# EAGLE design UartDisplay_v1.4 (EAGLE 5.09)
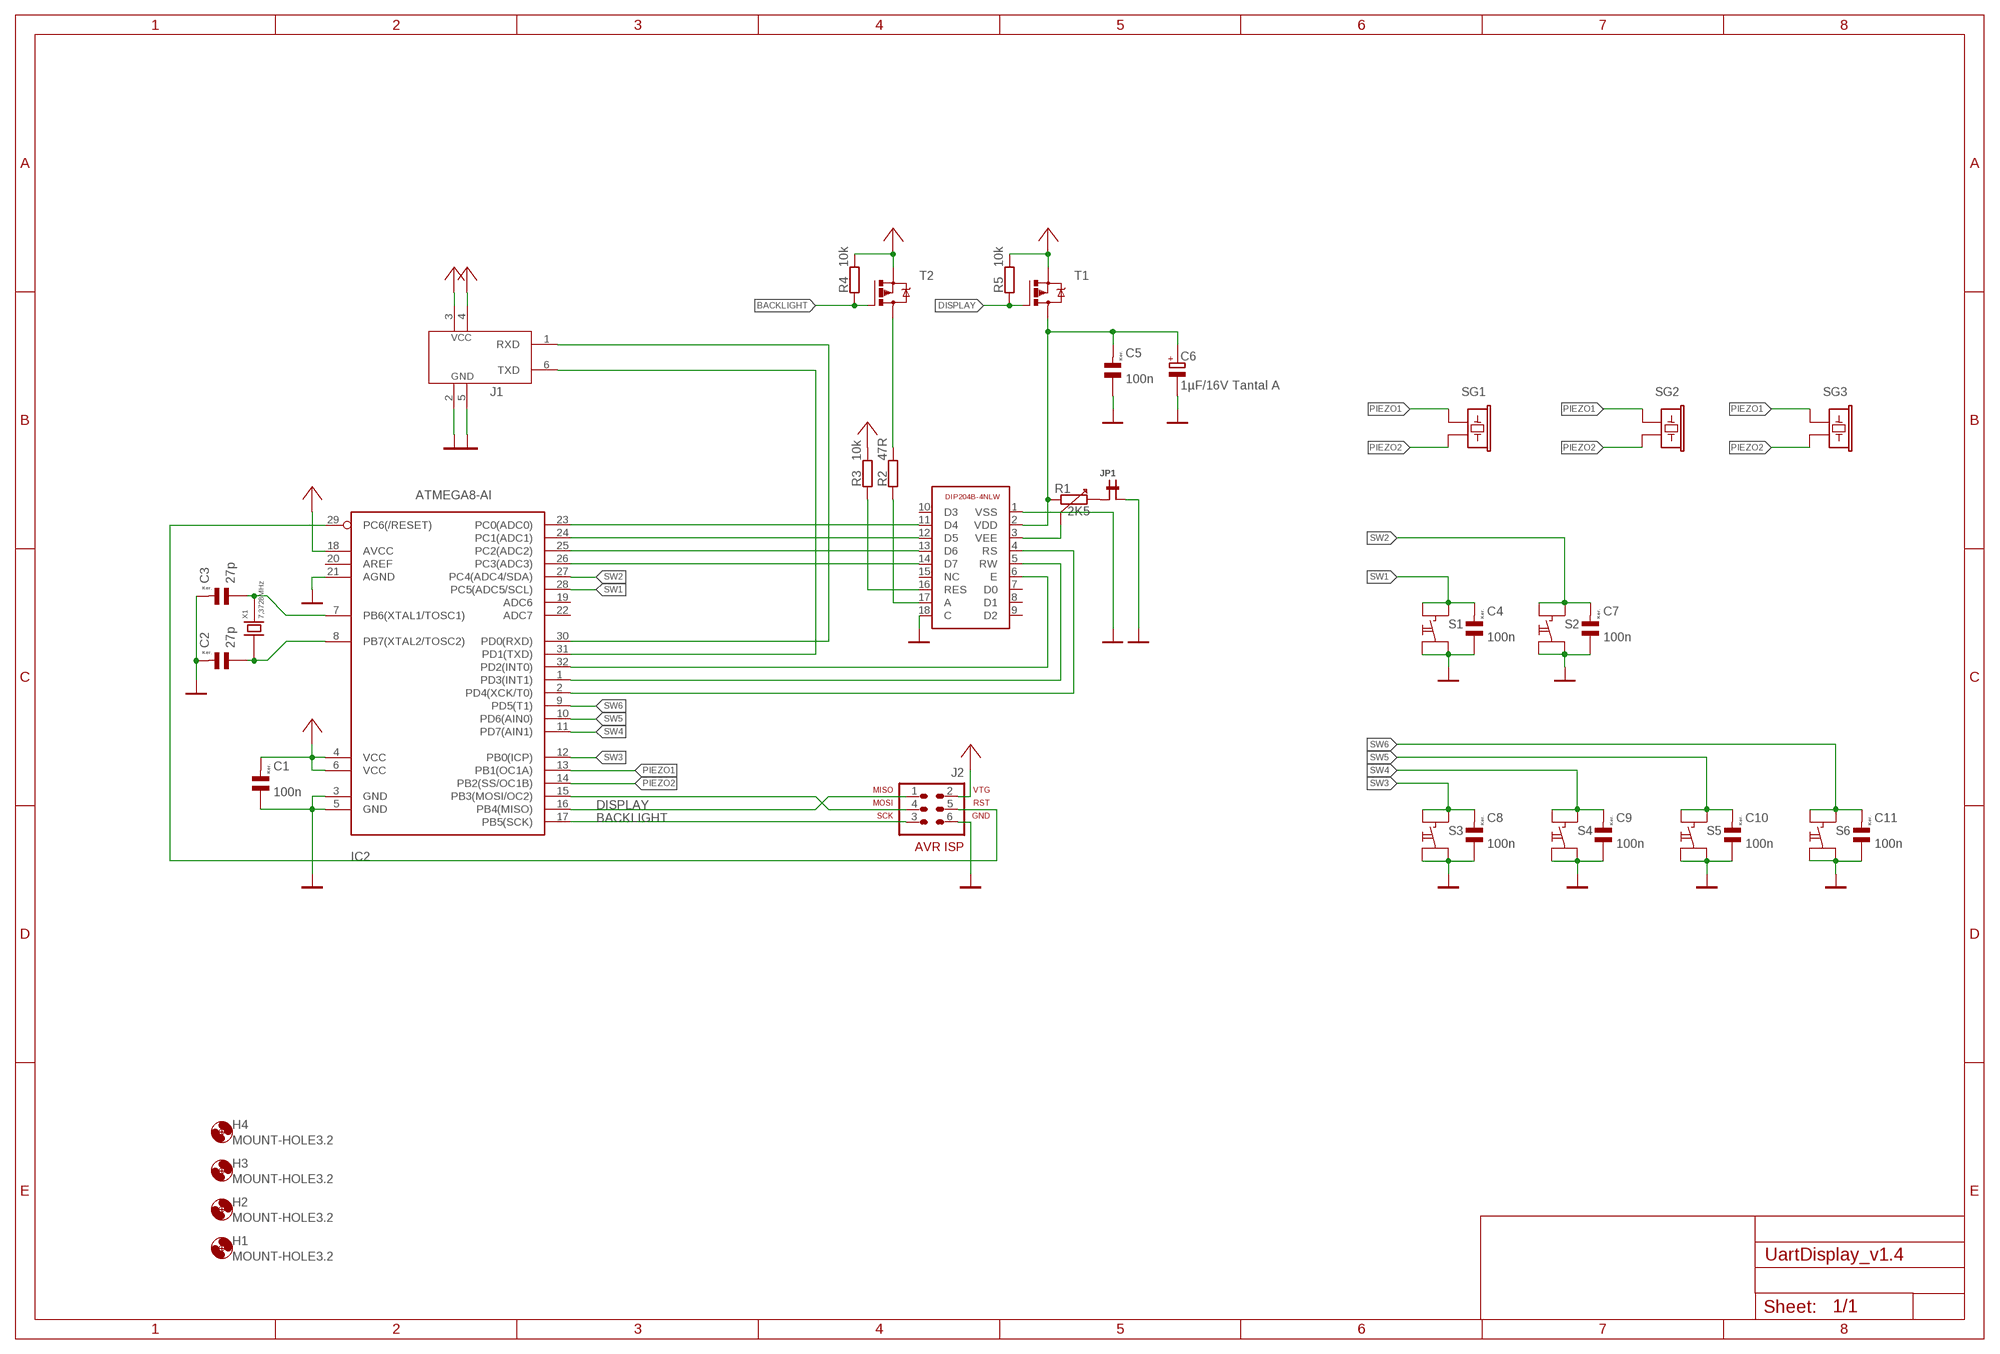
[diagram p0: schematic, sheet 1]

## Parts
C1  100n  C_KER_0805  [C0805K]
C2  27p  C_KER_0805  [C0805K]
C3  27p  C_KER_0805  [C0805K]
C4  100n  C_KER_0805  [C0805K]
C5  100n  C_KER_0805  [C0805K]
C6  1µF/16V Tantal A  ELKO_SMD_A  [SMC_A]
C7  100n  C_KER_0805  [C0805K]
C8  100n  C_KER_0805  [C0805K]
C9  100n  C_KER_0805  [C0805K]
C10  100n  C_KER_0805  [C0805K]
C11  100n  C_KER_0805  [C0805K]
H1  MOUNT-HOLE3.2  [3,2]
H2  MOUNT-HOLE3.2  [3,2]
H3  MOUNT-HOLE3.2  [3,2]
H4  MOUNT-HOLE3.2  [3,2]
IC1  DIP204B-4NLW  [DIP204B-4NLW]
IC2  ATMEGA8-AI  [TQFP32-08]
J1  RS232_6PINHW  [ML6L]
J2  AVR-ISP-6  [AVR-ISP-6]
JP1  JP1SMD  [JP2-0805]
R1  2K5  POTI_HOLE  [PT6-HOLE]
R2  47R  R_0805  [R0805]
R3  10k  R_0805  [R0805]
R4  10k  R_0805  [R0805]
R5  10k  R_0805  [R0805]
S1  PHAP3301  [PHAP3301]
S2  PHAP3301  [PHAP3301]
S3  PHAP3301  [PHAP3301]
S4  PHAP3301  [PHAP3301]
S5  PHAP3301  [PHAP3301]
S6  PHAP3301  [PHAP3301]
SG1  SIGNALGEBER_BJM05  [BJM05]
SG2  SIGNALGEBER_SMD  [PKLCS1212]
SG3  SIGNALGEBER_SMD  [PKLCS1212]
T1  P-FET-SOT23  [SOT23]
T2  P-FET-SOT23  [SOT23]
X1  7,3728MHz  CRYSTAL-HC49U-S  [HC49U-S]

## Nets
BACKLIGHT: IC2.17(PB5(SCK)) J2.3 R4.1 T2.1(G)
CONTRAST: IC1.3(VEE) R1.2
DISPLAY: IC2.16(PB4(MISO)) J2.1 R5.1 T1.1(G)
GND: C1.1 C2.2 C3.2 C4.1 C5.1 C6.- C7.1 C8.1 C9.1 C10.1 C11.1 IC1.1(VSS) IC1.18(C) IC2.3(GND) IC2.5(GND) IC2.21(AGND) J1.2(GND) J1.5(GND) J2.6 JP1.2 S1.3 S1.4 S2.3 S2.4 S3.3 S3.4 S4.3 S4.4 S5.3 S5.4 S6.3 S6.4
N$1: IC1.14(D7) IC2.26(PC3(ADC3))
N$2: IC1.13(D6) IC2.25(PC2(ADC2))
N$3: IC1.12(D5) IC2.24(PC1(ADC1))
N$4: IC1.11(D4) IC2.23(PC0(ADC0))
N$5: IC1.6(E) IC2.32(PD2(INT0))
N$6: IC1.5(RW) IC2.1(PD3(INT1))
N$7: IC1.4(RS) IC2.2(PD4(XCK/T0))
N$10: IC2.15(PB3(MOSI/OC2)) J2.4
N$11: IC2.29(PC6(/RESET)) J2.5
N$12: R2.2 T2.3(D)
N$13: JP1.1 R1.3
N$15: IC1.17(A) R2.1
N$16: IC1.16(RES) R3.1
N$327: C3.1 IC2.7(PB6(XTAL1/TOSC1)) X1.2
N$328: C2.1 IC2.8(PB7(XTAL2/TOSC2)) X1.1
PIEZO1: IC2.13(PB1(OC1A)) SG1.1 SG2.1 SG3.1
PIEZO2: IC2.14(PB2(SS/OC1B)) SG1.2 SG2.2 SG3.2
RXD: IC2.30(PD0(RXD)) J1.1(RXD)
SW1: C4.2 IC2.28(PC5(ADC5/SCL)) S1.1 S1.2
SW2: C7.2 IC2.27(PC4(ADC4/SDA)) S2.1 S2.2
SW3: C8.2 IC2.12(PB0(ICP)) S3.1 S3.2
SW4: C9.2 IC2.11(PD7(AIN1)) S4.1 S4.2
SW5: C10.2 IC2.10(PD6(AIN0)) S5.1 S5.2
SW6: C11.2 IC2.9(PD5(T1)) S6.1 S6.2
TXD: IC2.31(PD1(TXD)) J1.6(TXD)
VCC: C1.2 IC2.4(VCC) IC2.6(VCC) IC2.18(AVCC) J1.3(VCC) J1.4(VCC) J2.2 R3.2 R4.2 R5.2 T1.2(S) T2.2(S)
VDD: C5.2 C6.+ IC1.2(VDD) R1.1 T1.3(D)
Unconnected: IC1.7(D0) IC1.8(D1) IC1.9(D2) IC1.10(D3) IC1.15(NC) IC2.19(ADC6) IC2.20(AREF) IC2.22(ADC7)

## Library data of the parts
C1-C5 C7-C11 = lib-rcl:C_KER
C6 = lib-rcl:ELKO
H1-H4 = holes:MOUNT-HOLE: MOUNTING HOLE with drill center marker
IC1 = dip204b-4nlw:DIP204B-4NLW
IC2 = lib-avr:ATMEGA8: MICROCONTROLLER 8 Kbytes FLASH 1 kbytes SRAM 512 bytes EEPROM USART 6-channel 10 bit ADC 2-channel 8 bit ADC
J1 = lib-com:RS232_6PIN
J2 = lib-avr:AVR-ISP-6: AVR ISP-6 Serial Programming Header
JP1 = lib-connectors:JP1
R1 = lib-rcl:POTI?
R2-R5 = lib-rcl:R: RESISTOR, European symbol
S1-S6 = lib-switch:PHAP?*
SG1-SG3 = lib-misc:SIGNALGEBER: Piezo Summer
T1 T2 = lib-halbleiter:P-FET
X1 = lib-misc:CRYSTAL

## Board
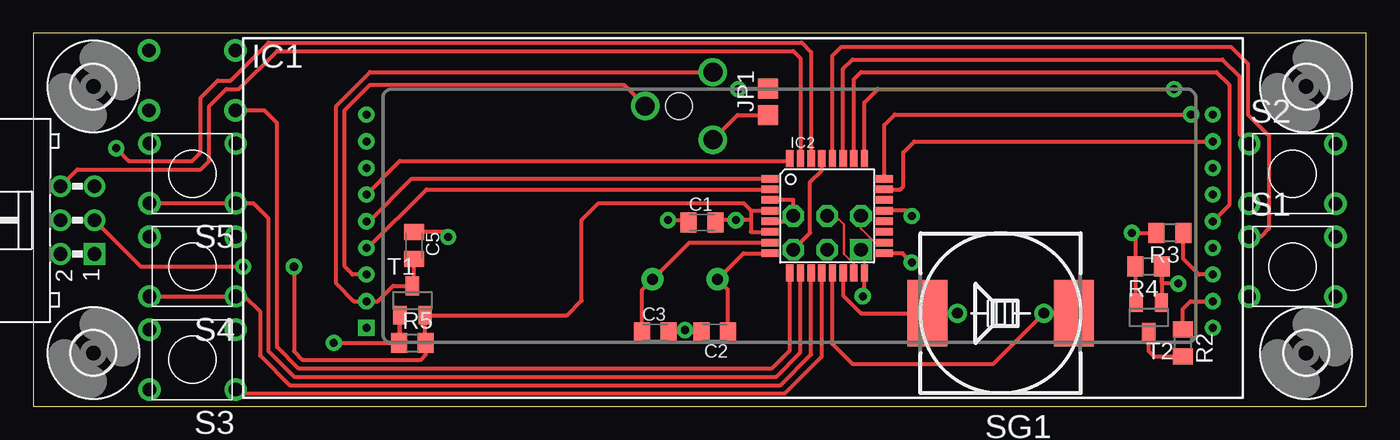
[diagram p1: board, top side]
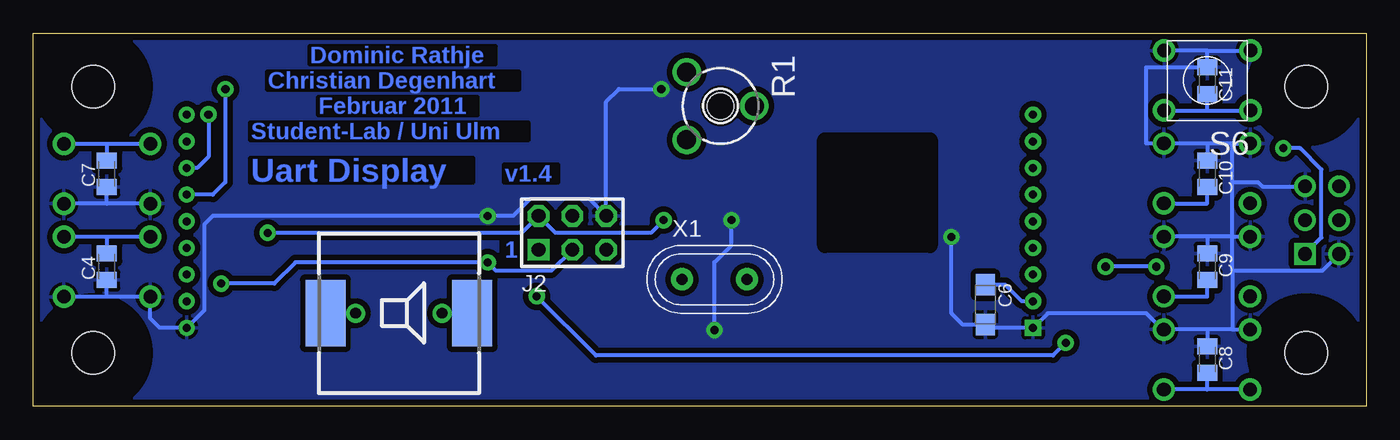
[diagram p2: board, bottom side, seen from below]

Size 100 x 28 mm. Coordinates in mm from the lower left corner, seen from the top.
Outline: 0,0 100,0 100,28 0,28 0,0
Copper layers (1*16): Top 0.0254mm / dielectric 1.4986mm / Bottom 0.0254mm
Design rules "uni_ulm *": minimum track width 8mil, minimum drill 16mil, track to track 8mil, track to pad 8mil, pad to pad 8mil, via to via 8mil, smd to smd 8mil, copper to edge 20mil, drill to drill 8mil, minimum pad ring 12mil, minimum via ring 12mil, stop-mask expansion 4mil, vias tented up to drill 24mil, thermal gap 10mil
bRestrict: 4 lines

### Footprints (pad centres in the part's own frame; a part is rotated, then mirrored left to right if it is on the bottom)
C0805K = smd 1.2 x 1.5: 1 -1,0; 2 1,0
SMC_A = smd 1.6 x 1.4: + -1.5,0; - 1.5,0
3,2 = hole 3.2: 0,0
DIP204B-4NLW = drill 0.6 square: 1 -26.945,-8.085 | drill 0.6 round: 2 -26.945,-6.085; 3 -26.945,-4.085; 4 -26.945,-2.085; 5 -26.945,-0.085; 6 -26.945,1.915; 7 -26.945,3.915; 8 -26.945,5.915; 9 -26.945,7.915; 10 36.555,7.915; 11 36.555,5.915; 12 36.555,3.915; 13 36.555,1.915; 14 36.555,-0.085; 15 36.555,-2.085; 16 36.555,-4.085; 17 36.555,-6.085; 18 36.555,-8.085
TQFP32-08 = smd 1.27 x 0.559: 1 -4.293,2.8; 2 -4.293,2; 3 -4.293,1.2; 4 -4.293,0.4; 5 -4.293,-0.4; 6 -4.293,-1.2; 7 -4.293,-2; 8 -4.293,-2.8; 17 4.293,-2.8; 18 4.293,-2; 19 4.293,-1.2; 20 4.293,-0.4; 21 4.293,0.4; 22 4.293,1.2; 23 4.293,2; 24 4.293,2.8 | smd 0.559 x 1.27: 9 -2.8,-4.293; 10 -2,-4.293; 11 -1.2,-4.293; 12 -0.4,-4.293; 13 0.4,-4.293; 14 1.2,-4.293; 15 2,-4.293; 16 2.8,-4.293; 25 2.8,4.293; 26 2,4.293; 27 1.2,4.293; 28 0.4,4.293; 29 -0.4,4.293; 30 -1.2,4.293; 31 -2,4.293; 32 -2.8,4.293
ML6L = drill 1.016 pad 1.626 square: 1 -2.54,-1.27 | drill 1.016 pad 1.626 round: 2 -2.54,1.27; 3 0,-1.27; 4 0,1.27; 5 2.54,-1.27; 6 2.54,1.27
AVR-ISP-6 = drill 1.016 square: 1 -2.54,-1.27 | drill 1.016 octagon: 2 -2.54,1.27; 3 0,-1.27; 4 0,1.27; 5 2.54,-1.27; 6 2.54,1.27
JP2-0805 = smd 1.5 x 1.5: 1 -1,0; 2 1,0
PT6-HOLE = drill 1.422 pad 2.032 round: 1 -2.54,-2.54; 2 0,2.54; 3 2.54,-2.54 | hole 2: 0,0
R0805 = smd 1.2 x 1.5: 1 -1,0; 2 1,0
PHAP3301 = drill 1.016 pad 1.676 round: 1 -2.235,-3.251; 2 -2.235,3.226; 3 2.261,-3.251; 4 2.261,3.226
BJM05 = drill 0.813 pad 1.422 round: 1 -3.25,0; 2 3.25,0
PKLCS1212 = smd 3 x 5: 1 -5.5,0; 2 5.5,0
SOT23 = smd 1 x 1.4: 1 -0.95,-1.1; 2 0.95,-1.1; 3 0,1.1
HC49U-S = drill 0.813 pad 1.676 round: 1 -2.44,0; 2 2.44,0

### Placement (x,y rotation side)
C1  50.16,13.79 0 top
C2  51.12,5.53 180 top
C3  46.67,5.53 0 top
C4  94.48,10.48 90 bottom
C5  28.57,12.06 270 top
C6  28.57,7.62 270 bottom
C7  94.48,17.46 90 bottom
C8  11.93,3.49 270 bottom
C9  11.93,10.48 270 bottom
C10  11.93,17.46 270 bottom
C11  11.93,24.45 270 bottom
H1  4.5,4 0 top
H2  4.5,24 0 top
H3  95.5,24 0 top
H4  95.5,4 0 top
IC1  51.93,13.97 0 top
IC2  59.55,14.29 0 top
J1  3.31,13.97 90 top
J2  59.55,13.02 0 bottom
JP1  55.11,22.86 90 top
R1  48.44,22.54 270 bottom
R2  86.23,4.76 270 top
R3  85.27,13.02 180 top
R4  83.69,10.48 180 top
R5  28.44,4.76 0 top
S1  94.48,10.48 270 top
S2  94.48,17.46 270 top
S3  11.93,3.49 90 top
S4  11.93,10.48 90 top
S5  11.93,17.46 90 top
S6  11.93,24.45 90 bottom
SG1  72.57,6.99 180 top
SG2  72.57,6.99 0 bottom
SG3  72.57,6.99 180 top
T1  28.44,7.94 0 top
T2  83.69,6.67 180 top
X1  48.89,9.53 0 bottom

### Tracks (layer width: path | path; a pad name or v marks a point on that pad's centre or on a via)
BACKLIGHT  (via drill 0.61 pad 0.81)
  Top 0.305: T2.1 84.68,7.82 R4.1 84.68,9.21 v85.91,9.21 | IC2.17 65.21,11.49 v65.9,10.79
  Bottom 0.305: v85.91,9.21 81.91,9.21 80.33,10.79 v65.9,10.79 65.27,10.16 61.14,10.16 J2.3
CONTRAST
  Top 0.305: IC1.3 23.95,9.88 23.36,10.48 23.36,22.23 25.26,24.13 44.31,24.13 R1.2 | R1.2
DISPLAY  (via drill 0.61 pad 0.81)
  Top 0.203: IC2.16 62.35,11.49 J2.1
  Top 0.305: 27.49,4.76 T1.1 27.49,4.81 R5.1 v22.54,4.76 | IC2.16 62.35,8.38 v62.23,8.26
  Bottom 0.305: v62.23,8.26 57.78,3.81 23.49,3.81 v22.54,4.76
GND  (via drill 0.61 pad 0.81)
  Top 0.305: v65.9,14.29 65.5,14.69 IC2.21 | IC2.3 57.01,15.49 J2.6 57.01,13.89 IC2.5 | JP1.2 52.93,23.86 v52.89,23.81 | C5.1 30.75,13.06 v31.11,12.7 | C3.2 C2.2 48.89,5.53 v48.89,5.71 | v47.62,13.97 48.98,13.97 C1.1
  Bottom 0.305: 94.48,8.22 S1.3 91.23,6.59 90.52,5.88 IC1.18 87.18,7.2 87.18,13.65 86.54,14.29 v65.9,14.29 64,14.29 62.73,15.56 58.28,15.56 J2.6 | 94.48,8.22 S1.4 | 94.48,15.2 S2.4 | S2.3 94.48,15.2 | 11.93,26.71 S6.3 | 11.93,26.71 S6.4 | 11.93,19.72 S5.3 16.51,19.72 16.51,25.45 C11.1 11.93,26.71 | 10.02,5.75 S3.4 | 11.93,19.72 C10.1 | 10.02,5.75 11.93,5.75 | 11.93,5.75 S3.3 15.31,5.88 15.41,5.88 16.51,6.99 23.89,6.99 IC1.1 28.57,5.88 C6.- 30.25,6.12 31.11,6.99 v31.11,12.7 | 11.93,5.75 C8.1 | 10.02,12.74 11.93,12.74 | 11.93,12.74 S4.3 | 11.93,12.74 C9.1 | 94.48,15.2 C7.1 | 94.48,8.22 C4.1 | 10.02,19.72 11.93,19.72 | 10.02,19.72 S5.4 | 10.02,12.74 10.02,16.83 | 10.02,16.83 10.02,19.72 | 10.02,12.74 S4.4 | 10.02,10.16 10.02,5.75 | 10.02,10.16 10.02,12.74 | J1.5 7.8,16.51 8.12,16.83 10.02,16.83 | J1.2 3.31,10.16 10.02,10.16 | v52.89,23.81 56.06,23.81 57.01,22.86 J2.6 | J2.6 56.7,13.97 | v47.62,13.97 47.62,12.06 48.89,10.79 v48.89,5.71
  pour Bottom (isolate 0.406, rank 2): -0.13,28.26 -0.13,-0.32 100.2,-0.32 100.2,28.26
  pour Bottom: 59.56,15.56 84.32,15.56 84.32,28.26 60.83,28.26 60.83,23.81 59.56,22.54
N$1
  Top 0.305: 61.46,18.68 IC2.26 61.55,24.54 62.09,25.08 88.76,25.08 89.72,24.13 89.72,15.11 IC1.14
N$2  (via drill 0.61 pad 0.81)
  Top 0.305: IC2.25 62.35,22.8 63.36,23.81 v85.59,23.81
  Bottom 0.305: v85.59,23.81 85.59,16.83 86.53,15.88 IC1.13
N$3  (via drill 0.61 pad 0.81)
  Top 0.305: IC2.24 63.85,21.12 64.63,21.91 v86.86,21.91
  Bottom 0.305: IC1.12 87.71,17.89 86.86,18.73 v86.86,21.91
N$4
  Top 0.305: IC2.23 65.05,16.29 65.27,16.51 65.27,19.05 66.1,19.89 IC1.11
N$5
  Top 0.305: IC1.6 26.1,16.99 26.1,17.02 27.49,18.41 56.59,18.41 IC2.32
N$6
  Top 0.305: IC1.5 25.18,13.88 28.38,17.09 IC2.1
N$7
  Top 0.305: IC1.4 25.08,11.88 29.49,16.29 IC2.2
N$10
  Top 0.203: IC2.15 61.55,10.7 60.82,11.43 | J2.4 60.19,14.29 60.82,13.65 60.82,11.43 | 60.82,11.43
  Top 0.305: IC2.15 61.46,9.9
N$11
  Top 0.305: IC2.29 59.15,17.7 58.28,16.83 58.28,13.02 J2.5
N$12
  Top 0.305: R2.2 84.05,3.76 83.68,4.13 T2.3
N$13
  Top 0.305: JP1.1 52.84,21.86 R1.3
N$15
  Top 0.305: IC1.17 86.81,7.88 86.22,7.3 R2.1
N$16
  Top 0.305: R3.1 86.27,11.06 87.45,9.88 IC1.16
N$327
  Top 0.305: IC2.7 49.22,12.29 X1.2 45.67,8.74 C3.1
N$328
  Top 0.305: IC2.8 53.3,11.49 X1.1 52.12,8.74 C2.1
PIEZO1
  Top 0.305: IC2.13 59.95,4.68 61.46,3.17 72.01,3.17 SG1.1 SG3.1
  Bottom 0.305: SG1.1 SG3.1
PIEZO2
  Top 0.305: IC2.14 60.75,8.32 62.09,6.99 SG1.2 SG3.2
  Bottom 0.305: SG1.2 SG3.2
RXD  (via drill 0.61 pad 0.81)
  Top 0.305: IC2.30 58.35,26.6 57.65,27.3 17.64,27.3 14.79,24.45 13.83,24.45 12.56,23.18 12.56,19.05 11.93,18.41 7.17,18.41 v6.21,19.37
  Bottom 0.305: J1.1 3.36,12.65 3.36,17.78 4.94,19.37 v6.21,19.37
SW1
  Top 0.305: S1.1 92.09,12.71 92.71,13.34 92.71,20.32 91.12,21.91 91.12,25.72 89.85,26.99 60.64,26.99 59.95,26.3 IC2.28
  Bottom 0.305: S1.1 94.48,12.71 | 94.48,12.71 S1.2 | 94.48,12.71 C4.2
SW2
  Top 0.305: IC2.27 60.75,25.33 61.46,26.04 89.22,26.04 90.49,24.77 90.49,20.44 S2.1
  Bottom 0.305: S2.1 94.48,19.7 | 94.48,19.7 S2.2 | 94.48,19.7 C7.2
SW3
  Top 0.305: IC2.12 59.15,3.73 56.38,0.95 15.49,0.95 S3.1
  Bottom 0.305: S3.2 11.93,1.26 | 11.93,1.26 S3.1 | 11.93,1.26 C8.2
SW4
  Top 0.305: S4.2 S4.1 | S4.1 15.43,8.24 | IC2.11 58.35,3.88 56.06,1.59 19.23,1.59 17.01,3.81 17.01,7.12 15.87,8.26 15.19,8.26 S4.1
  Bottom 0.305: C9.2 11.93,8.24 S4.1
SW5
  Top 0.305: S5.2 S5.1 16.52,15.23 17.64,14.11 17.64,4.13 19.55,2.22 55.74,2.22 57.55,4.03 IC2.10
  Bottom 0.305: C10.2 11.93,15.23 S5.1
SW6
  Top 0.305: IC2.9 56.75,4.18 55.43,2.86 19.87,2.86 18.28,4.45 18.28,21.27 17.34,22.21 S6.2
  Bottom 0.305: S6.2 11.93,22.21 | 11.93,22.21 C11.2 | 11.93,22.21 S6.1
TXD
  Top 0.305: IC2.31 57.55,26.13 57.01,26.67 18.28,26.67 15.42,23.81 14.47,23.81 13.2,22.54 13.2,18.41 12.56,17.78 3.31,17.78 J1.6
VCC  (via drill 0.61 pad 0.81)
  Top 0.203: IC2.18 63.14,12.29 62.09,13.34 J2.2
  Top 0.305: J1.4 J1.3 8.07,10.48 v15.74,10.48 | IC2.6 53.84,13.09 53.84,13.97 | 53.84,14.69 IC2.4 | R3.2 v82.41,13.02 82.68,12.75 R4.2 82.68,7.82 T2.2 | v19.55,10.48 19.55,4.13 20.18,3.49 29.07,3.49 29.44,3.86 R5.2 29.39,4.81 T1.2 40.04,6.84 41.14,7.94 41.14,13.97 42.41,15.24 53.29,15.24 53.84,14.69 | 53.84,14.69 53.84,13.97 | 53.84,13.97 v52.7,13.97 51.16,13.97 C1.2
  Bottom 0.305: v82.41,13.02 63.36,13.02 J2.2 60.82,13.02 53.66,13.02 v52.7,13.97 | v15.74,10.48 v19.55,10.48
VDD
  Top 0.305: R1.1 25.26,25.08 22.72,22.54 22.72,9.21 24.05,7.88 IC1.2 25.85,7.88 27,9.04 T1.3 28.57,9.17 C5.2
  Bottom 0.305: C6.+ 27.08,9.12 25.85,7.88 IC1.2

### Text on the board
Bottom: Dominic Rathje | Christian Degenhart | Februar 2011 | Student-Lab / Uni Ulm | v1.4 | Uart Display | 1
Measures: alle Maße in mm | ( 28 / 0) | ( 28 / 100) | ( 0 / 0 ) | ( 0 / 100)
